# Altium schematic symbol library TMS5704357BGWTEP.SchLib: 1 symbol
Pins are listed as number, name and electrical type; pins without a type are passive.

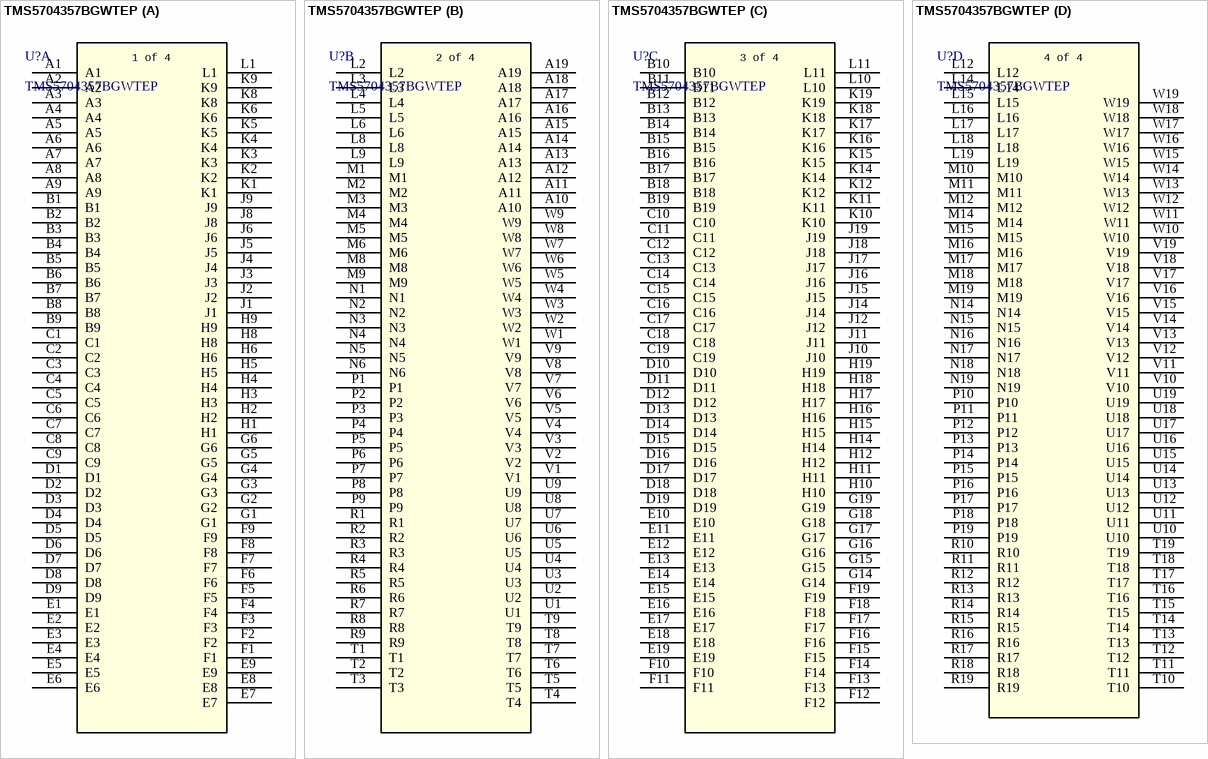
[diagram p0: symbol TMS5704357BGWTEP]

## TMS5704357BGWTEP
designator U?
Enhanced product, 16/32 bit RISC flash MCU, Arm Cortex-R5F, EMAC, FlexRay 337-NFBGA -55 to 125; Manufacturer_Name: Texas Instruments
footprint BGA_GWTEP_TEX
part A pins: A1, A2, A3, A4, A5, A6, A7, A8, A9, B1, B2, B3, B4, B5, B6, B7, B8, B9, C1, C2, C3, C4, C5, C6, C7, C8, C9, D1, D2, D3, D4, D5, D6, D7, D8, D9, E1, E2, E3, E4, E5, E6, E7, E8, E9, F1, F2, F3, F4, F5, F6, F7, F8, F9, G1, G2, G3, G4, G5, G6, H1, H2, H3, H4, H5, H6, H8, H9, J1, J2, J3, J4, J5, J6, J8, J9, K1, K2, K3, K4, K5, K6, K8, K9, L1
part B pins: A10, A11, A12, A13, A14, A15, A16, A17, A18, A19, L2, L3, L4, L5, L6, L8, L9, M1, M2, M3, M4, M5, M6, M8, M9, N1, N2, N3, N4, N5, N6, P1, P2, P3, P4, P5, P6, P7, P8, P9, R1, R2, R3, R4, R5, R6, R7, R8, R9, T1, T2, T3, T4, T5, T6, T7, T8, T9, U1, U2, U3, U4, U5, U6, U7, U8, U9, V1, V2, V3, V4, V5, V6, V7, V8, V9, W1, W2, W3, W4, W5, W6, W7, W8, W9
part C pins: B10, B11, B12, B13, B14, B15, B16, B17, B18, B19, C10, C11, C12, C13, C14, C15, C16, C17, C18, C19, D10, D11, D12, D13, D14, D15, D16, D17, D18, D19, E10, E11, E12, E13, E14, E15, E16, E17, E18, E19, F10, F11, F12, F13, F14, F15, F16, F17, F18, F19, G14, G15, G16, G17, G18, G19, H10, H11, H12, H14, H15, H16, H17, H18, H19, J10, J11, J12, J14, J15, J16, J17, J18, J19, K10, K11, K12, K14, K15, K16, K17, K18, K19, L10, L11
part D pins: L12, L14, L15, L16, L17, L18, L19, M10, M11, M12, M14, M15, M16, M17, M18, M19, N14, N15, N16, N17, N18, N19, P10, P11, P12, P13, P14, P15, P16, P17, P18, P19, R10, R11, R12, R13, R14, R15, R16, R17, R18, R19, T10, T11, T12, T13, T14, T15, T16, T17, T18, T19, U10, U11, U12, U13, U14, U15, U16, U17, U18, U19, V10, V11, V12, V13, V14, V15, V16, V17, V18, V19, W10, W11, W12, W13, W14, W15, W16, W17, W18, W19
